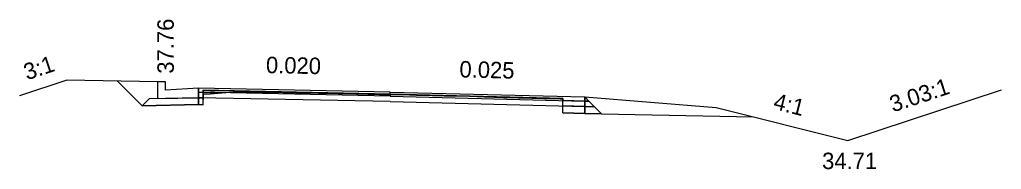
# Model space of a CAD drawing. Extents: x 2192944 to 2203363, y 83241 to 89279.
# Drawn here: x 2203233.7 to 2203293.4, y 85751.2 to 85760.3 of the extents above; entities that cross this region are included whole.
import ezdxf

# ---------------------------------------------------------------- set-up
doc = ezdxf.new("R2010")
doc.units = 0
for name, color, linetype in [('Prop CMT Conc Surface', 7, 'Continuous'), ('Prop CMT Concrete Structures', 7, 'Continuous'), ('Prop CMT Pvmt Course 1', 7, 'Continuous'), ('Prop CMT Pvmt Course 1 CG', 7, 'Continuous'), ('Prop CMT Pvmt Course 1 Wedge', 7, 'Continuous'), ('Prop CMT Pvmt Course 2', 7, 'Continuous'), ('Prop CMT Pvmt Course 2 Wedge', 7, 'Continuous'), ('Prop CMT Pvmt Course 3', 7, 'Continuous'), ('Prop CMT Pvmt Surface', 7, 'Continuous'), ('Prop CMT Pvmt Surface Shoulder', 7, 'Continuous'), ('Prop CMT Pvmt Wedge Surface 1', 7, 'Continuous'), ('Prop CMT Pvmt Wedge Surface 2', 7, 'Continuous'), ('Prop CMT Pvmt Wedge Surface 3', 7, 'Continuous'), ('Prop CMT Shld Paved Course 1', 7, 'Continuous'), ('Prop CMT Shld Paved Course 2', 7, 'Continuous'), ('Prop CMT Shld Paved Course 3', 7, 'Continuous'), ('Prop CMT Slope Grass', 7, 'Continuous'), ('Prop CMT Subgrade Earthwork', 7, 'Continuous'), ('Prop XS Ditch Standard Text', 7, 'Continuous'), ('Prop XS Hydro Elevations', 7, 'Continuous'), ('Prop XS SE Text', 7, 'Continuous'), ('Prop XS Side Slope Text', 7, 'Continuous')]:
    doc.layers.add(name, color=color, linetype=linetype)

msp = doc.modelspace()

# ---------------------------------------------------------------- linework, layer by layer
at = {"layer": 'Prop CMT Conc Surface'}
for points in [[(2203242.576, 85755.985), (2203242.575, 85756.485), (2203242.075, 85756.485)], [(2203244.576, 85756.105), (2203242.576, 85755.985)]]:
    msp.add_lwpolyline(points, dxfattribs=at)
at = {"layer": 'Prop CMT Concrete Structures'}
for points in [[(2203244.576, 85756.105), (2203242.576, 85755.985), (2203242.575, 85756.485), (2203242.075, 85756.485)], [(2203242.075, 85756.485), (2203242.076, 85755.471), (2203244.576, 85755.521)], [(2203244.576, 85755.521), (2203244.576, 85756.105)]]:
    msp.add_lwpolyline(points, dxfattribs=at)
at = {"layer": 'Prop CMT Pvmt Course 1'}
for points in [[(2203256.225, 85755.869), (2203244.576, 85756.105)], [(2203244.576, 85756.105), (2203244.576, 85755.855)], [(2203244.576, 85755.855), (2203244.859, 85755.849)], [(2203244.859, 85755.849), (2203244.859, 85755.974)], [(2203244.859, 85755.974), (2203256.225, 85755.744)], [(2203256.225, 85755.619), (2203256.225, 85755.869)], [(2203256.225, 85755.869), (2203268.067, 85755.573)], [(2203256.225, 85755.619), (2203256.225, 85755.869)], [(2203256.225, 85755.744), (2203256.225, 85755.619), (2203256.225, 85755.619)], [(2203266.742, 85755.481), (2203256.225, 85755.744)], [(2203256.225, 85755.744), (2203256.225, 85755.619), (2203256.225, 85755.619)], [(2203266.742, 85755.356), (2203266.742, 85755.481)], [(2203268.067, 85755.573), (2203268.067, 85755.323)], [(2203268.067, 85755.323), (2203266.742, 85755.356)]]:
    msp.add_lwpolyline(points, dxfattribs=at)
at = {"layer": 'Prop CMT Pvmt Course 1 CG'}
for points in [[(2203244.576, 85755.521), (2203241.576, 85755.461), (2203241.151, 85755.036)], [(2203244.576, 85755.105), (2203244.576, 85755.521)], [(2203241.151, 85755.036), (2203244.576, 85755.105)]]:
    msp.add_lwpolyline(points, dxfattribs=at)
at = {"layer": 'Prop CMT Pvmt Course 1 Wedge'}
for points in [[(2203244.859, 85755.974), (2203245.31, 85755.965), (2203246.695, 85755.937), (2203247.471, 85755.921), (2203247.957, 85755.911), (2203248.034, 85755.91), (2203248.204, 85755.906), (2203249.734, 85755.875), (2203250.467, 85755.86), (2203250.549, 85755.859), (2203250.652, 85755.857), (2203253.065, 85755.808), (2203253.483, 85755.799), (2203255.58, 85755.757), (2203255.652, 85755.755), (2203256.225, 85755.744)], [(2203244.859, 85755.849), (2203244.859, 85755.974)], [(2203256.225, 85755.698), (2203255.652, 85755.702), (2203255.58, 85755.701), (2203253.483, 85755.754), (2203253.065, 85755.764), (2203250.652, 85755.801), (2203250.549, 85755.802), (2203250.467, 85755.803), (2203249.734, 85755.816), (2203248.204, 85755.841), (2203248.034, 85755.844), (2203247.957, 85755.844), (2203247.471, 85755.836), (2203246.695, 85755.856), (2203246.246, 85755.821), (2203245.31, 85755.84), (2203244.859, 85755.849)], [(2203256.225, 85755.744), (2203256.225, 85755.698)], [(2203256.225, 85755.744), (2203256.838, 85755.728), (2203257.407, 85755.714), (2203257.838, 85755.703), (2203258.096, 85755.697), (2203259.52, 85755.661), (2203260.611, 85755.634), (2203261.977, 85755.6), (2203263.127, 85755.571), (2203264.046, 85755.548), (2203265.642, 85755.508), (2203265.793, 85755.504), (2203266.145, 85755.496), (2203266.58, 85755.485), (2203266.742, 85755.481)], [(2203256.225, 85755.698), (2203256.225, 85755.744)], [(2203266.742, 85755.407), (2203266.58, 85755.429), (2203266.145, 85755.449), (2203265.793, 85755.457), (2203265.642, 85755.46), (2203264.046, 85755.501), (2203263.127, 85755.526), (2203261.977, 85755.562), (2203260.611, 85755.609), (2203259.52, 85755.629), (2203258.096, 85755.655), (2203257.838, 85755.663), (2203257.407, 85755.679), (2203256.838, 85755.694), (2203256.225, 85755.698)], [(2203266.742, 85755.481), (2203266.742, 85755.407)]]:
    msp.add_lwpolyline(points, dxfattribs=at)
at = {"layer": 'Prop CMT Pvmt Course 2'}
for points in [[(2203244.859, 85755.849), (2203244.576, 85755.855)], [(2203244.576, 85755.855), (2203244.576, 85755.521)], [(2203244.576, 85755.521), (2203244.859, 85755.516)], [(2203244.859, 85755.516), (2203244.859, 85755.849)], [(2203266.742, 85755.022), (2203266.742, 85755.356)], [(2203266.742, 85755.356), (2203268.067, 85755.323)], [(2203268.067, 85754.989), (2203266.742, 85755.022)], [(2203268.067, 85755.323), (2203268.067, 85754.989)]]:
    msp.add_lwpolyline(points, dxfattribs=at)
at = {"layer": 'Prop CMT Pvmt Course 2 Wedge'}
for points in [[(2203244.859, 85755.849), (2203245.31, 85755.84), (2203246.246, 85755.821)], [(2203244.859, 85755.712), (2203244.859, 85755.849)], [(2203246.246, 85755.821), (2203245.31, 85755.747), (2203244.859, 85755.712)]]:
    msp.add_lwpolyline(points, dxfattribs=at)
at = {"layer": 'Prop CMT Pvmt Course 3'}
for points in [[(2203244.859, 85755.516), (2203244.576, 85755.521)], [(2203244.576, 85755.521), (2203244.576, 85755.105)], [(2203244.859, 85755.099), (2203244.859, 85755.516)], [(2203244.576, 85755.105), (2203244.859, 85755.099)], [(2203266.742, 85755.022), (2203268.067, 85754.989)], [(2203266.742, 85754.606), (2203266.742, 85755.022)], [(2203268.067, 85754.989), (2203268.067, 85754.573)], [(2203268.067, 85754.573), (2203266.742, 85754.606)]]:
    msp.add_lwpolyline(points, dxfattribs=at)
at = {"layer": 'Prop CMT Pvmt Surface'}
for points in [[(2203256.225, 85755.869), (2203244.576, 85756.105)], [(2203256.225, 85755.869), (2203268.067, 85755.573)]]:
    msp.add_lwpolyline(points, dxfattribs=at)
at = {"layer": 'Prop CMT Pvmt Surface Shoulder'}
msp.add_lwpolyline([(2203268.067, 85755.573), (2203268.067, 85755.573)], dxfattribs=at)
at = {"layer": 'Prop CMT Pvmt Wedge Surface 1'}
for points in [[(2203244.576, 85755.855), (2203244.576, 85756.105)], [(2203244.859, 85755.849), (2203244.576, 85755.855)], [(2203256.225, 85755.744), (2203244.859, 85755.974)], [(2203244.859, 85755.974), (2203244.859, 85755.849)], [(2203256.225, 85755.744), (2203266.742, 85755.481)], [(2203266.742, 85755.481), (2203266.742, 85755.356)], [(2203268.067, 85755.323), (2203268.067, 85755.573)], [(2203266.742, 85755.356), (2203268.067, 85755.323)]]:
    msp.add_lwpolyline(points, dxfattribs=at)
at = {"layer": 'Prop CMT Pvmt Wedge Surface 2'}
for points in [[(2203244.576, 85755.855), (2203244.576, 85756.105)], [(2203256.225, 85755.619), (2203244.576, 85755.855)], [(2203256.225, 85755.619), (2203268.067, 85755.323)], [(2203268.067, 85755.323), (2203268.067, 85755.573)]]:
    msp.add_lwpolyline(points, dxfattribs=at)
at = {"layer": 'Prop CMT Pvmt Wedge Surface 3'}
for points in [[(2203244.576, 85755.521), (2203244.576, 85756.105)], [(2203256.225, 85755.285), (2203244.576, 85755.521)], [(2203268.067, 85754.989), (2203268.067, 85755.573)], [(2203256.225, 85755.285), (2203268.067, 85754.989)]]:
    msp.add_lwpolyline(points, dxfattribs=at)
at = {"layer": 'Prop CMT Shld Paved Course 1'}
for points in [[(2203268.067, 85755.573), (2203268.067, 85755.573)], [(2203268.067, 85755.573), (2203268.322, 85755.317)], [(2203268.067, 85755.323), (2203268.067, 85755.573)], [(2203268.322, 85755.317), (2203268.067, 85755.323)]]:
    msp.add_lwpolyline(points, dxfattribs=at)
at = {"layer": 'Prop CMT Shld Paved Course 2'}
for points in [[(2203268.067, 85755.323), (2203268.322, 85755.317), (2203268.662, 85754.977)], [(2203268.067, 85754.989), (2203268.067, 85755.323)], [(2203268.662, 85754.977), (2203268.067, 85754.989)]]:
    msp.add_lwpolyline(points, dxfattribs=at)
at = {"layer": 'Prop CMT Shld Paved Course 3'}
for points in [[(2203268.067, 85754.989), (2203268.662, 85754.977)], [(2203268.067, 85754.573), (2203268.067, 85754.989)], [(2203268.662, 85754.977), (2203268.662, 85754.977)], [(2203268.662, 85754.977), (2203269.087, 85754.552)], [(2203269.087, 85754.552), (2203268.067, 85754.573)]]:
    msp.add_lwpolyline(points, dxfattribs=at)
at = {"layer": 'Prop CMT Slope Grass'}
for points in [[(2203242.075, 85756.485), (2203236.575, 85756.595), (2203233.7, 85755.636)], [(2203268.067, 85755.573), (2203276.067, 85754.933), (2203284.067, 85752.933), (2203293.401, 85756.013)]]:
    msp.add_lwpolyline(points, dxfattribs=at)
at = {"layer": 'Prop CMT Subgrade Earthwork'}
for points in [[(2203244.576, 85755.105), (2203241.151, 85755.036), (2203239.654, 85756.533)], [(2203244.859, 85755.099), (2203244.874, 85755.713)], [(2203244.859, 85755.099), (2203244.576, 85755.105)], [(2203266.742, 85754.606), (2203266.741, 85755.407)], [(2203266.742, 85754.606), (2203268.067, 85754.573)], [(2203268.067, 85754.573), (2203269.087, 85754.552)], [(2203269.087, 85754.552), (2203278.327, 85754.367)]]:
    msp.add_lwpolyline(points, dxfattribs=at)

# ---------------------------------------------------------------- texts
at = {"layer": 'Prop XS Ditch Standard Text'}
msp.add_text('34.71', height=1, dxfattribs=at).set_placement((2203282.5, 85751.183))
at = {"layer": 'Prop XS Hydro Elevations'}
msp.add_text('37.76', height=1, rotation=90, dxfattribs=at).set_placement((2203243.076, 85756.985))
at = {"layer": 'Prop XS SE Text'}
for s, rotation, p in [('0.020', 358.8382, (2203248.671, 85757.022)), ('0.025', 358.5679, (2203260.437, 85756.764))]:
    msp.add_text(s, height=1, rotation=rotation, dxfattribs=at).set_placement(p)
at = {"layer": 'Prop XS Side Slope Text'}
for s, rotation, p in [('3:1', 18.43323, (2203234.149, 85756.577)), ('3.03:1', 18.26289, (2203286.807, 85754.627)), ('4:1', 345.96376, (2203279.479, 85754.852))]:
    msp.add_text(s, height=1, rotation=rotation, dxfattribs=at).set_placement(p)

doc.saveas('drawing.dxf')
